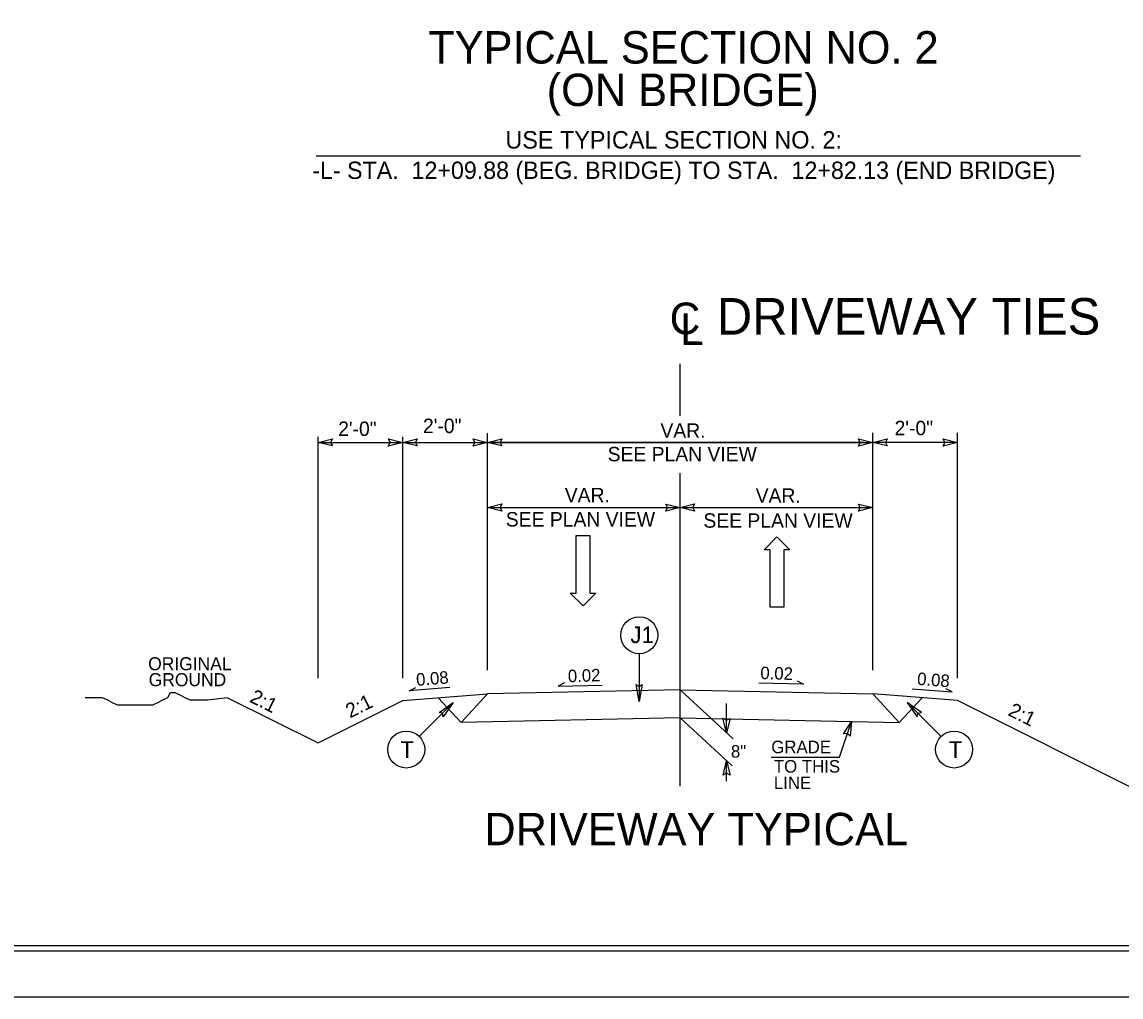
# Model space of a CAD drawing. Extents: x 574067 to 574470, y -53282 to -53062.
# Drawn here: x 574197 to 574304, y -53282.1 to -53187.2 of the extents above; entities that cross this region are included whole.
import ezdxf

# ---------------------------------------------------------------- set-up
doc = ezdxf.new("R2010")
doc.units = 0
for name, color, linetype in [('Old_Level_1', 7, 'Continuous'), ('Old_Level_11', 7, 'Continuous'), ('Old_Level_2', 7, 'Continuous'), ('Old_Level_3', 7, 'Continuous'), ('Old_Level_60', 7, 'Continuous'), ('Prop Dimension', 7, 'Continuous'), ('Prop Dimension Text', 7, 'Continuous'), ('Prop Lane Arrow CELL', 7, 'Continuous'), ('Sheet Cutting Line CELL', 7, 'Continuous'), ('Sheet Plot Border Inside CELL', 7, 'Continuous'), ('Sheet Plot Border Outside CELL', 7, 'Continuous'), ('Sheet Typical CELL', 7, 'Continuous'), ('Typical Berm CELL', 7, 'Continuous'), ('Typical Berm Information CELL', 7, 'Continuous'), ('Typical Grade Point Symbol CELL', 7, 'Continuous'), ('Typical ID Circle CELL', 7, 'Continuous'), ('Typical Pavement Slope CELL', 7, 'Continuous'), ('Typical Slope Point Local CELL', 7, 'Continuous'), ('Typical Terminator CELL', 7, 'Continuous'), ('Typical Text Centerline CELL', 7, 'Continuous'), ('Typical Text General CELL', 7, 'Continuous'), ('Typical Text Grade Point CELL', 7, 'Continuous'), ('Typical Text ID Circle CELL', 7, 'Continuous')]:
    doc.layers.add(name, color=color, linetype=linetype)

# ---------------------------------------------------------------- blocks, each defined once
blk = doc.blocks.new('TERMINATOR')
at = {"layer": 'Typical Terminator CELL'}
blk.add_lwpolyline([(-0.469, 0.081), (0, 0), (-0.471, -0.083), (-0.411, 0)], close=True, dxfattribs=at)

msp = doc.modelspace()

# ---------------------------------------------------------------- linework, layer by layer
at = {"layer": 'Old_Level_11'}
msp.add_line((574225.68, -53200.2), (574300.08, -53200.2), dxfattribs=at)
at = {"layer": 'Old_Level_2'}
for p, q in [((574261.11, -53225.51), (574261.11, -53220.46)), ((574261.11, -53261.58), (574261.11, -53231.09))]:
    msp.add_line(p, q, dxfattribs=at)
at = {"layer": 'Prop Dimension'}
msp.add_line((574288.11, -53228.11), (574279.86, -53228.11), dxfattribs=at)
at = {"layer": 'Prop Dimension Text'}
for p, q in [((574242.36, -53250.29), (574242.36, -53227.22)), ((574279.86, -53250.29), (574279.86, -53227.18)), ((574288.11, -53251.08), (574288.11, -53227.18)), ((574225.86, -53251.08), (574225.86, -53227.58)), ((574225.86, -53228.11), (574279.86, -53228.11)), ((574234.11, -53251.08), (574234.11, -53227.58)), ((574279.02, -53228.11), (574242.36, -53228.11)), ((574242.36, -53234.46), (574279.86, -53234.46)), ((574261.11, -53252.21), (574266.27, -53256.98)), ((574265.63, -53256.38), (574265.63, -53253.54)), ((574261.11, -53254.94), (574266.18, -53259.61)), ((574265.63, -53261.1), (574265.63, -53259.11))]:
    msp.add_line(p, q, dxfattribs=at)
at = {"layer": 'Prop Lane Arrow CELL'}
for p, q in [((574250.99, -53242.78), (574250.99, -53237.18)), ((574250.99, -53237.18), (574252.31, -53237.18)), ((574252.31, -53237.18), (574252.31, -53242.78)), ((574269.27, -53238.57), (574270.51, -53237.31)), ((574270.51, -53237.31), (574271.79, -53238.57)), ((574269.87, -53238.57), (574269.27, -53238.57)), ((574269.87, -53244.17), (574269.87, -53238.57)), ((574271.79, -53238.57), (574271.19, -53238.57)), ((574271.19, -53238.57), (574271.19, -53244.17)), ((574251.67, -53244.04), (574250.39, -53242.78)), ((574250.39, -53242.78), (574250.99, -53242.78)), ((574252.91, -53242.78), (574251.67, -53244.04)), ((574252.31, -53242.78), (574252.91, -53242.78)), ((574271.19, -53244.17), (574269.87, -53244.17))]:
    msp.add_line(p, q, dxfattribs=at)
at = {"layer": 'Sheet Cutting Line CELL'}
msp.add_line((574066.93, -53282.12), (574403.73, -53282.12), dxfattribs=at)
at = {"layer": 'Sheet Plot Border Inside CELL'}
msp.add_lwpolyline([(574402.83, -53066.61), (574069.53, -53066.61), (574069.53, -53277.63), (574402.83, -53277.63)], close=True, dxfattribs=at)
at = {"layer": 'Sheet Plot Border Outside CELL'}
msp.add_lwpolyline([(574403.73, -53062.12), (574066.93, -53062.12), (574066.93, -53282.12), (574403.73, -53282.12)], close=True, dxfattribs=at)
at = {"layer": 'Sheet Typical CELL'}
msp.add_lwpolyline([(574400.33, -53067.12), (574100.33, -53067.12), (574100.33, -53277.12), (574400.33, -53277.12)], close=True, dxfattribs=at)
at = {"layer": 'Typical Berm CELL'}
for p, q in [((574239.78, -53255.38), (574237.55, -53252.98)), ((574239.78, -53255.38), (574242.36, -53252.6)), ((574261.11, -53252.21), (574242.36, -53252.6)), ((574261.11, -53252.21), (574279.86, -53252.6)), ((574282.44, -53255.38), (574279.86, -53252.6)), ((574282.44, -53255.38), (574284.67, -53252.98)), ((574261.11, -53254.94), (574239.78, -53255.38)), ((574261.11, -53254.94), (574282.44, -53255.38))]:
    msp.add_line(p, q, dxfattribs=at)
at = {"layer": 'Typical Berm Information CELL'}
for p, q in [((574249.86, -53251.53), (574249.24, -53251.84)), ((574249.24, -53251.84), (574253.52, -53251.75)), ((574273.11, -53251.64), (574268.78, -53251.56)), ((574272.49, -53251.33), (574273.11, -53251.64))]:
    msp.add_line(p, q, dxfattribs=at)
at = {"layer": 'Typical Grade Point Symbol CELL'}
msp.add_line((574276.62, -53258.76), (574277.78, -53255.28), dxfattribs=at)
at = {"layer": 'Typical ID Circle CELL'}
for p, q in [((574257.13, -53248.69), (574257.13, -53253.35)), ((574235.72, -53256.74), (574239.02, -53253.45)), ((574286.5, -53256.74), (574283.2, -53253.45))]:
    msp.add_line(p, q, dxfattribs=at)
for centre in [(574257.13, -53246.89), (574234.45, -53258.02), (574287.77, -53258.02)]:
    msp.add_circle(centre, 1.8, dxfattribs=at)
at = {"layer": 'Typical Pavement Slope CELL'}
for p, q in [((574238.7, -53251.98), (574234.74, -53252.3)), ((574234.74, -53252.3), (574235.37, -53251.98)), ((574283.7, -53252.1), (574287.6, -53252.41)), ((574287.6, -53252.41), (574286.98, -53252.1))]:
    msp.add_line(p, q, dxfattribs=at)
at = {"layer": 'Typical Slope Point Local CELL'}
for p, q in [((574217.06, -53252.98), (574225.86, -53257.38)), ((574234.11, -53253.26), (574242.36, -53252.6)), ((574288.11, -53253.26), (574279.86, -53252.6)), ((574225.86, -53257.38), (574234.11, -53253.26)), ((574306.25, -53262.33), (574288.11, -53253.26))]:
    msp.add_line(p, q, dxfattribs=at)
msp.add_lwpolyline([(574217.06, -53252.98), (574215.11, -53253.22), (574214.63, -53253.22), (574213.9, -53253.22), (574213.41, -53253.22), (574212.92, -53252.98), (574212.44, -53252.74), (574211.95, -53252.49), (574211.46, -53252.49), (574211.22, -53252.98), (574210.73, -53253.22), (574210.25, -53253.47), (574209.76, -53253.71), (574209.28, -53253.71), (574208.79, -53253.71), (574208.3, -53253.71), (574207.82, -53253.71), (574207.33, -53253.71), (574206.84, -53253.71), (574206.36, -53253.71), (574205.87, -53253.47), (574205.39, -53253.22), (574204.9, -53252.98), (574204.17, -53252.98), (574203.68, -53252.98), (574203.2, -53252.98)], dxfattribs=at)
at = {"layer": 'Typical Terminator CELL'}
for points in [[(574257.42, -53251.68), (574257.13, -53253.35), (574256.83, -53251.67), (574257.13, -53251.88)], [(574237.64, -53254.42), (574239.02, -53253.45), (574238.04, -53254.84), (574237.98, -53254.48)], [(574284.59, -53254.42), (574283.2, -53253.45), (574284.18, -53254.84), (574284.24, -53254.48)]]:
    msp.add_lwpolyline(points, close=True, dxfattribs=at)
at = {"layer": 'Typical Text Grade Point CELL'}
msp.add_line((574269.98, -53258.76), (574276.62, -53258.76), dxfattribs=at)

# ---------------------------------------------------------------- block references
at = {"layer": 'Old_Level_11'}
for p, xscale, yscale, rotation in [((574225.86, -53228.11), 2.9825026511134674, 4.280821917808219, 180), ((574234.11, -53228.11), 2.9825026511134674, 4.280821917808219, 180), ((574242.36, -53228.11), 2.9825026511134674, 4.280821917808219, 180), ((574279.86, -53228.11), 2.9825026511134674, 4.280821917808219, 180), ((574242.36, -53234.46), 2.9825026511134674, 4.280821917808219, 180), ((574261.11, -53234.46), 2.9825026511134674, 4.280821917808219, 180), ((574265.63, -53256.38), 2.9825026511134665, 4.280821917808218, -90.00000000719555), ((574277.78, -53255.28), 2.982502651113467, 4.280821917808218, 71.56505117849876), ((574265.63, -53259.11), 2.9825026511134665, 4.280821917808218, 90.00000000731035)]:
    msp.add_blockref('TERMINATOR', p, dxfattribs=dict(at, xscale=xscale, yscale=yscale, rotation=rotation))
at = {"layer": 'Old_Level_11', "xscale": 2.9825026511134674, "yscale": 4.280821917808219}
for p in [(574234.11, -53228.11), (574242.36, -53228.11), (574279.86, -53228.11), (574288.11, -53228.11), (574261.11, -53234.46), (574279.86, -53234.46)]:
    msp.add_blockref('TERMINATOR', p, dxfattribs=at)

# ---------------------------------------------------------------- texts
at = {"layer": 'Old_Level_1'}
for s, p in [('ORIGINAL ', (574209.33, -53250.3)), ('GROUND', (574209.38, -53251.85))]:
    msp.add_text(s, height=1.27, dxfattribs=at).set_placement(p)
at = {"layer": 'Old_Level_11'}
for s, height, p in [('USE TYPICAL SECTION NO. 2:', 1.7021, (574244.1, -53199.49)), ('DRIVEWAY TIES', 3.5625, (574264.68, -53217.61))]:
    msp.add_text(s, height=height, dxfattribs=at).set_placement(p)
at = {"layer": 'Old_Level_3'}
for s, p in [('TYPICAL SECTION NO. 2', (574236.59, -53191.21)), ('(ON BRIDGE)', (574248.12, -53195.35)), ('DRIVEWAY TYPICAL', (574242.05, -53267.34))]:
    msp.add_text(s, height=3.1536, dxfattribs=at).set_placement(p)
at = {"layer": 'Old_Level_60'}
msp.add_text('-L- STA.  12+09.88 (BEG. BRIDGE) TO STA.  12+82.13 (END BRIDGE)', height=1.6899, dxfattribs=at).set_placement((574225.3, -53202.45))
at = {"layer": 'Prop Dimension Text'}
for s, height, p in [('2\'-0"', 1.406, (574227.82, -53227.48)), ('2\'-0"', 1.406, (574236.08, -53227.2)), ('VAR.', 1.406, (574259.19, -53227.66)), ('2\'-0"', 1.406, (574281.98, -53227.41)), ('SEE PLAN VIEW', 1.4062, (574254.05, -53229.95)), ('VAR.', 1.406, (574249.88, -53233.94)), ('VAR.', 1.406, (574268.46, -53233.99)), ('SEE PLAN VIEW', 1.4062, (574244.14, -53236.3)), ('SEE PLAN VIEW', 1.4062, (574263.37, -53236.42))]:
    msp.add_text(s, height=height, dxfattribs=at).set_placement(p)
msp.add_text('0.08 ', height=1.217, rotation=355.4261, dxfattribs=at).set_placement((574284.14, -53251.71))
at = {"layer": 'Typical Berm CELL'}
msp.add_text('0.08', height=1.217, rotation=4.5739, dxfattribs=at).set_placement((574235.46, -53251.83))
at = {"layer": 'Typical Berm Information CELL'}
for rotation, p in [(1.8084, (574250.2, -53251.47)), (358.1916, (574268.9, -53251.15))]:
    msp.add_text('0.02', height=1.217, rotation=rotation, dxfattribs=at).set_placement(p)
at = {"layer": 'Typical Slope Point Local CELL'}
msp.add_text('2:1', height=1.406, rotation=26.5659, dxfattribs=at).set_placement((574228.99, -53254.99))
at = {"layer": 'Typical Text Centerline CELL'}
msp.add_text('C', height=3.08, dxfattribs=at).set_placement((574260.09, -53217.57))
msp.add_text('L', height=3.08, rotation=359.9469, dxfattribs=at).set_placement((574261.11, -53218.62))
at = {"layer": 'Typical Text General CELL'}
for p in [(574219.12, -53253.34), (574292.94, -53254.65)]:
    msp.add_text('2:1', height=1.399, rotation=333.4349, dxfattribs=at).set_placement(p)
at = {"layer": 'Typical Text Grade Point CELL'}
for s, p in [('GRADE', (574269.98, -53258.38)), ('8"', (574266.05, -53258.81)), ('TO THIS', (574270.23, -53260.27)), ('LINE', (574270.23, -53261.87))]:
    msp.add_text(s, height=1.223, dxfattribs=at).set_placement(p)
at = {"layer": 'Typical Text ID Circle CELL'}
for s, height, p in [('J1', 1.614, (574256.27, -53247.65)), ('T', 1.61, (574233.88, -53258.83)), ('T', 1.61, (574287.25, -53258.83))]:
    msp.add_text(s, height=height, dxfattribs=at).set_placement(p)

doc.saveas('drawing.dxf')
